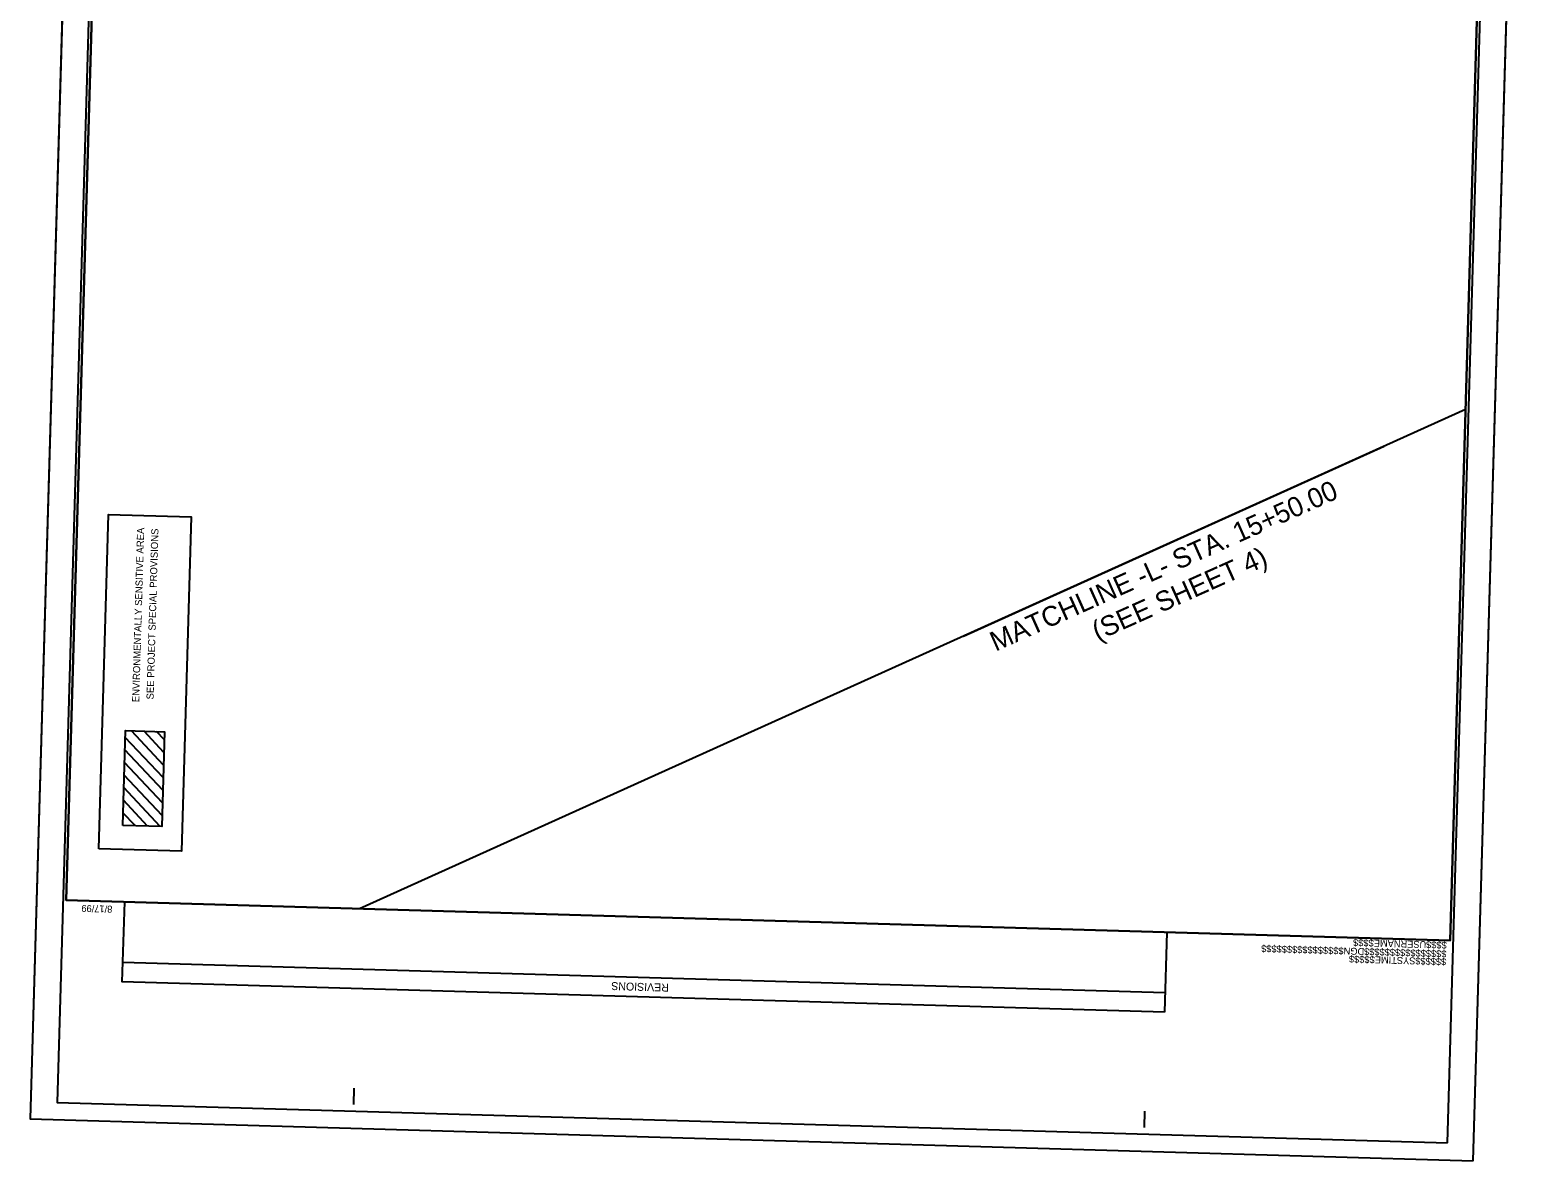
# Model space of a CAD drawing. Extents: x 2096987 to 2098161, y 681809 to 686842.
# Drawn here: x 2096987 to 2098130, y 685128 to 685985 of the extents above; entities that cross this region are included whole.
import ezdxf

# ---------------------------------------------------------------- set-up
doc = ezdxf.new("R2010")
doc.units = 0
for name, color, linetype in [('Default', 7, 'Continuous'), ('Matchline', 7, 'Continuous'), ('Prop North Arrow NAD83 for Plan Sheets CELL', 7, 'Continuous'), ('Scratch_Level_6', 7, 'Continuous'), ('Sheet Block Title CELL', 7, 'Continuous'), ('Sheet Data Field CELL', 7, 'Continuous'), ('Sheet Plan And Profile CELL', 7, 'Continuous'), ('Sheet Plan CELL', 7, 'Continuous'), ('Sheet Plot Border Inside CELL', 7, 'Continuous'), ('Sheet Sticker Exception Certification CELL', 7, 'Continuous')]:
    doc.layers.add(name, color=color, linetype=linetype)

msp = doc.modelspace()

# ---------------------------------------------------------------- linework, layer by layer
at = {"layer": 'Default'}
for p, q in [((2097087.8, 685418.4), (2097058.9, 685448.9)), ((2097088, 685427.9), (2097063.6, 685453.8)), ((2097088.3, 685437.4), (2097073.2, 685453.5)), ((2097088.6, 685447), (2097082.7, 685453.3)), ((2097087.5, 685408.8), (2097058.6, 685439.4)), ((2097087.2, 685399.3), (2097058.3, 685429.8)), ((2097086.9, 685389.7), (2097058.1, 685420.3)), ((2097075.9, 685381.7), (2097057.5, 685401.2)), ((2097085.5, 685381.4), (2097057.8, 685410.8)), ((2097066.4, 685382), (2097057.2, 685391.7))]:
    msp.add_line(p, q, dxfattribs=at)
for points in [[(2097039, 685364.5), (2097046.3, 685618), (2097109, 685616.2), (2097101.7, 685362.7)], [(2097057, 685382.2), (2097059, 685454), (2097088.8, 685453.1), (2097086.7, 685381.4)]]:
    msp.add_lwpolyline(points, close=True, dxfattribs=at)
at = {"layer": 'Prop North Arrow NAD83 for Plan Sheets CELL'}
msp.add_line((2097694.7, 685525.6), (2098013.7, 685669.6), dxfattribs=at)
at = {"layer": 'Scratch_Level_6'}
msp.add_lwpolyline([(2097039, 685364.5), (2097046.3, 685618), (2097109, 685616.2), (2097101.7, 685362.7)], close=True, dxfattribs=at)
at = {"layer": 'Sheet Block Title CELL'}
msp.add_lwpolyline([(2098081.3, 685127.8), (2098130.3, 686810.6), (2097035.7, 686842.4), (2096986.8, 685159.6)], close=True, dxfattribs=at)
at = {"layer": 'Sheet Data Field CELL'}
msp.add_lwpolyline([(2098061.7, 685141.4), (2098110.1, 686806.7), (2097055.6, 686837.4), (2097007.2, 685172.1)], close=True, dxfattribs=at)
at = {"layer": 'Sheet Plan And Profile CELL'}
for p, q in [((2097035.7, 686842.4), (2096986.8, 685159.6)), ((2098081.3, 685127.8), (2098130.3, 686810.6)), ((2096986.8, 685159.6), (2098081.3, 685127.8))]:
    msp.add_line(p, q, dxfattribs=at)
at = {"layer": 'Sheet Plan CELL'}
msp.add_line((2097847.4, 685255.2), (2097057.1, 685278.2), dxfattribs=at)
msp.add_lwpolyline([(2097847, 685240.6), (2097056.7, 685263.6), (2097058.5, 685324.1), (2097848.8, 685301.2)], close=True, dxfattribs=at)
at = {"layer": 'Sheet Plot Border Inside CELL'}
msp.add_lwpolyline([(2098075.4, 685697.4), (2097236.7, 685318.9), (2097014.1, 685325.4), (2097046, 686421.2), (2097047.2, 686463.8), (2097051.9, 686624.8), (2097288.1, 686618), (2097291.4, 686731.2), (2098104.7, 686707.5)], close=True, dxfattribs=at)
msp.add_lwpolyline([(2098075.4, 685697.4), (2097236.7, 685318.9), (2097014.1, 685325.4), (2097046, 686421.2), (2097047.2, 686463.8), (2097051.9, 686624.8), (2097288.1, 686618), (2097291.4, 686731.2), (2098104.7, 686707.5)], close=True, dxfattribs=at)
at = {"layer": 'Sheet Sticker Exception Certification CELL'}
for p, q in [((2097014.1, 685325.4), (2097014.1, 685325.4)), ((2098063.7, 685294.9), (2098063.7, 685294.9)), ((2097232.2, 685170.5), (2097232.6, 685183)), ((2097832, 685153.1), (2097832.3, 685165.6))]:
    msp.add_line(p, q, dxfattribs=at)
for points in [[(2097057.7, 686824.8), (2097014.1, 685325.4), (2098063.7, 685294.9), (2098107.3, 686794.3)], [(2098063.7, 685294.9), (2097014.1, 685325.4), (2097051.9, 686624.8), (2097201.9, 686620.5), (2097207.7, 686820.4), (2098107.3, 686794.3)]]:
    msp.add_lwpolyline(points, close=True, dxfattribs=at)

# ---------------------------------------------------------------- texts
at = {"layer": 'Default'}
for s, p in [('ENVIRONMENTALLY SENSITIVE AREA', (2097069.5, 685475.5)), ('SEE PROJECT SPECIAL PROVISIONS', (2097080.4, 685477.6))]:
    msp.add_text(s, height=5.4, rotation=88.3404, dxfattribs=at).set_placement(p)
at = {"layer": 'Matchline'}
for s, p in [('MATCHLINE -L- STA. 15+50.00', (2097719, 685513.8)), ('(SEE SHEET 4)', (2097796.4, 685521.8))]:
    msp.add_text(s, height=15, rotation=24.122, dxfattribs=at).set_placement(p)
at = {"layer": 'Sheet Plan CELL'}
msp.add_text('REVISIONS', height=6, rotation=178.3348, dxfattribs=at).set_placement((2097471.3, 685262.1))
at = {"layer": 'Sheet Sticker Exception Certification CELL'}
for s, p in [('8/17/99', (2097049.2, 685321.2)), ('$$$$$$$$$$$$$$$$DGN$$$$$$$$$$$$$$$$', (2098061.1, 685287.3)), ('$$$$USERNAME$$$$', (2098061.3, 685293.9)), ('$$$$$$SYSTIME$$$$$', (2098060.9, 685281.3))]:
    msp.add_text(s, height=5.25, rotation=178.3348, dxfattribs=at).set_placement(p)

doc.saveas('drawing.dxf')
